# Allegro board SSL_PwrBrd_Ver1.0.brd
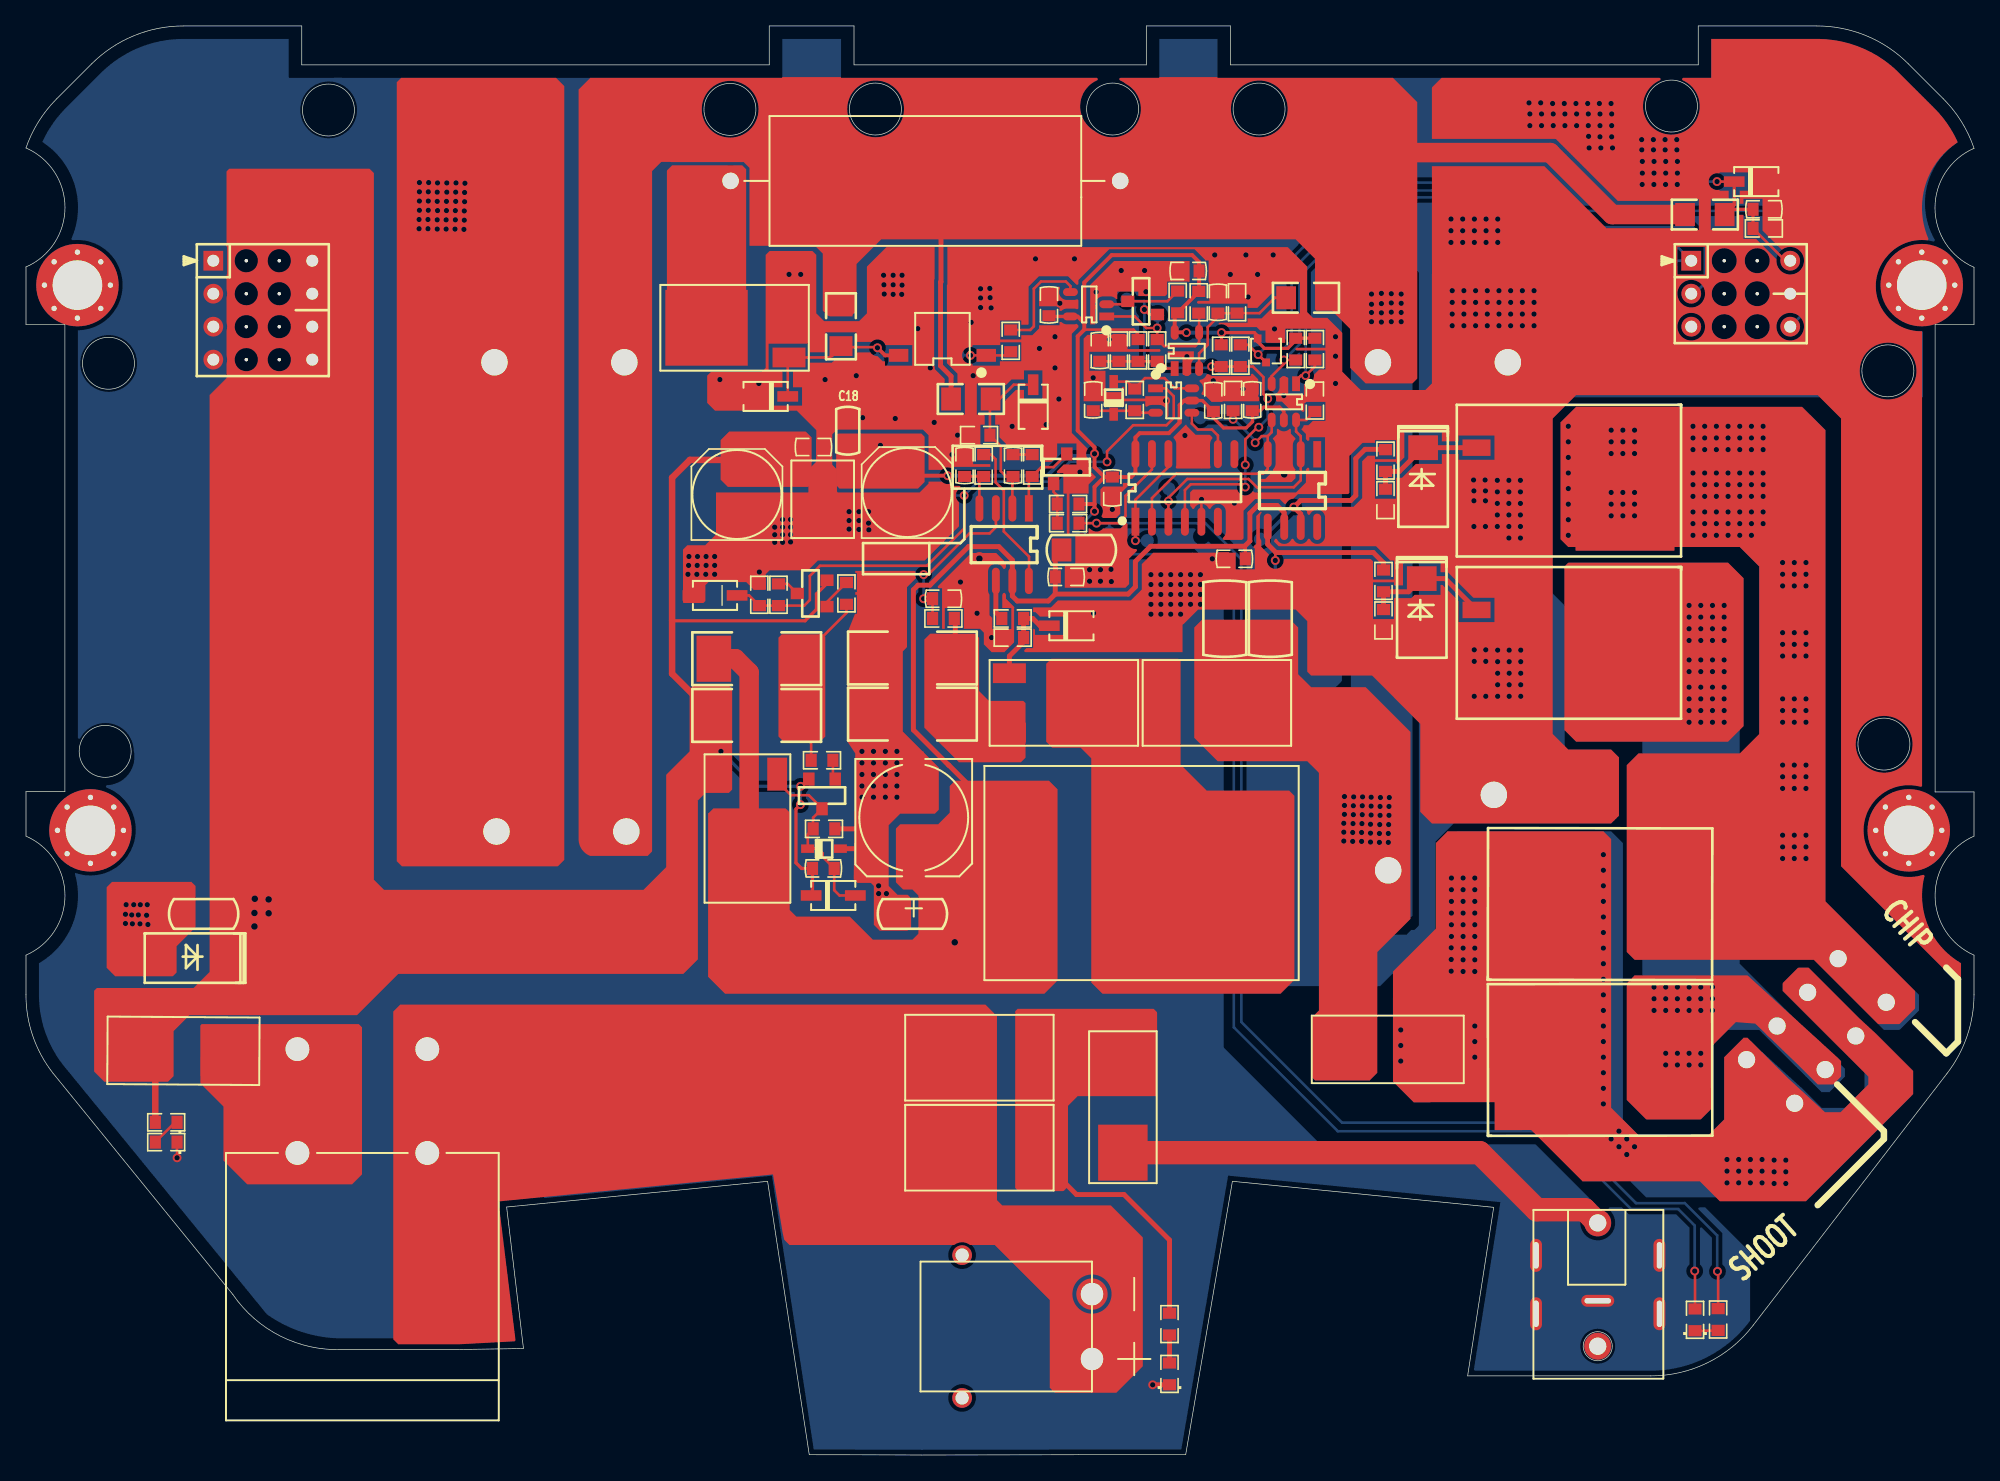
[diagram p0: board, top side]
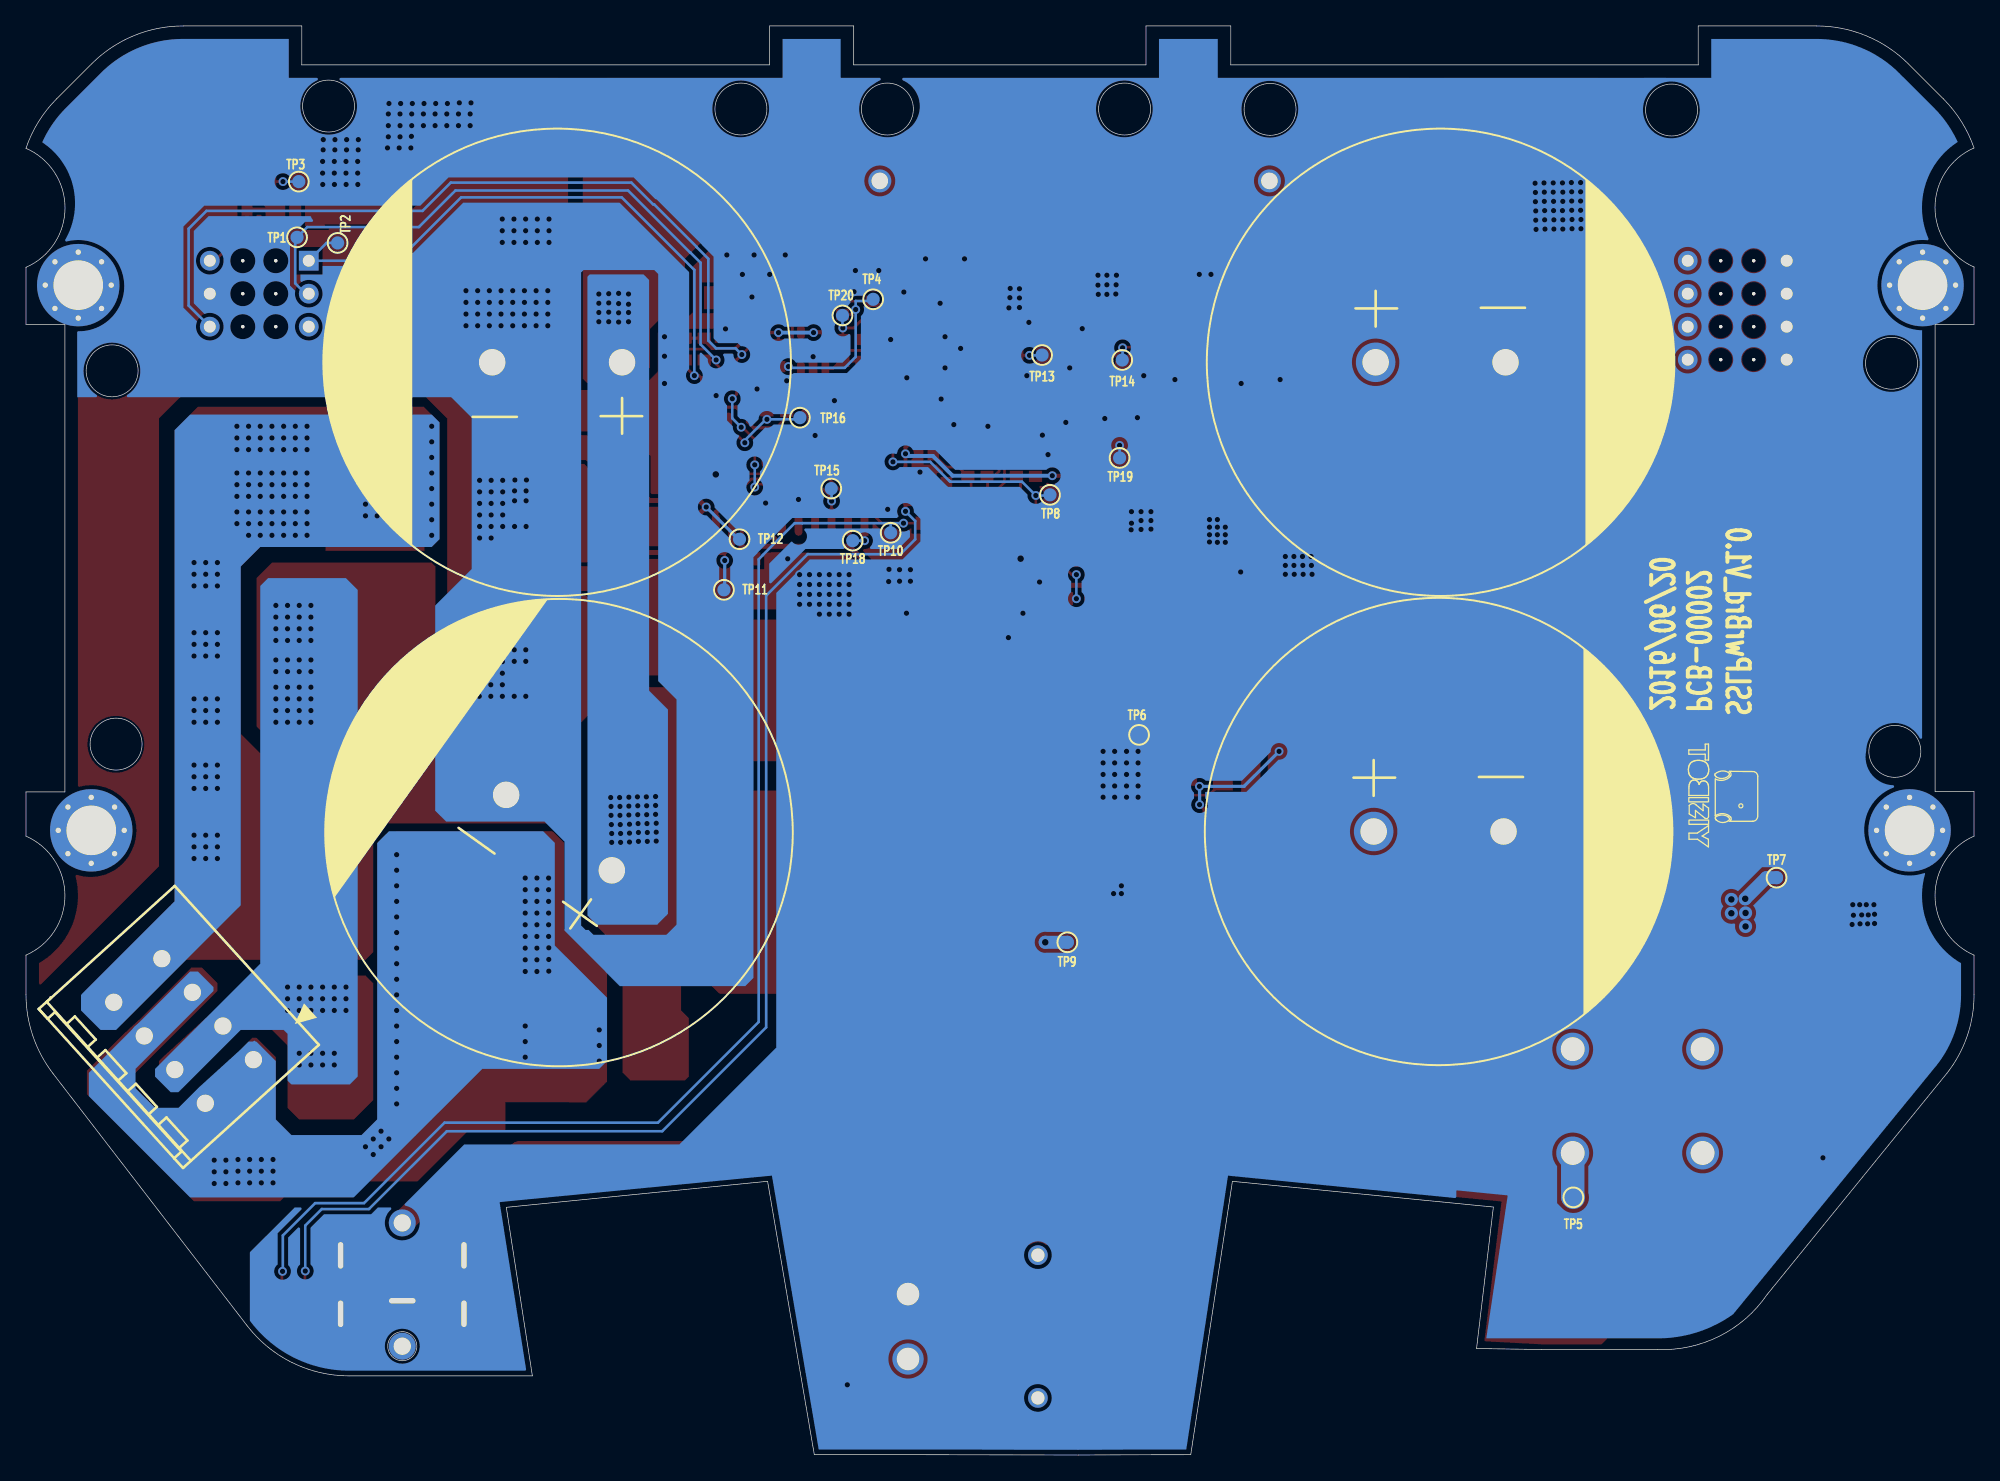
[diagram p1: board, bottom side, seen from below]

Outline 149.99 x 110.08 mm; copper layers: TOP, BOTTOM. Coordinates in mm from the lower left corner of the outline.
Outline path: circle c6.1,54.2 r2 ; circle c6.35,84.1 r2 ; circle c23.29,103.61 r2 ; circle c54.2,103.66 r2 ; circle c65.4,103.68 r2 ; circle c83.66,103.68 r2 ; circle c94.94,103.68 r2 ; circle c121.01,8.38 r1.12 ; circle c126.69,103.91 r2 ; circle c143.05,54.76 r2 ; circle c143.35,83.52 r2 ; 0,100.69 arc(3,96.1) 0,91.52 0,87.1 3,87.1 3,51.1 0,51.1 0,47.68 arc(3,43.09) 0,38.51 0,35.48 arc(0.53,32.27) 2.08,29.41 15.93,12.37 arc(19.61,9.15) 24.38,8.13 33.3,8.13 38.3,8.2 37.01,19.1 57.1,21.09 60.31,0.03 arc(64.64,0.02) 68.97,0 81.06,0.03 89.29,0.03 92.89,21.09 113,19.08 111,6.1 125.07,6.1 arc(129.49,7.12) 132.99,10.01 147.9,29.39 arc(149.45,32.26) 149.99,35.48 149.99,38.51 arc(146.99,43.09) 149.99,47.68 149.99,51.08 146.99,51.08 146.99,87.1 149.99,87.1 149.99,91.49 arc(146.98,96.08) 149.99,100.66 arc(149.03,102.7) 147.62,104.47 144.93,107.16 arc(141.68,109.34) 137.85,110.08 128.75,110.08 128.75,107.09 92.74,107.09 92.74,110.08 86.26,110.08 86.26,107.09 63.75,107.09 63.75,110.08 57.23,110.08 57.23,107.09 21.23,107.09 21.23,110.08 12.14,110.08 arc(8.31,109.33) 5.05,107.16 2.36,104.47 arc(0.97,102.71) 0,100.69 ; 2.5,90.12 arc(4,91.62) 5.5,90.12 arc(4,88.62) 2.5,90.12 ; 3.5,48.13 arc(5,49.63) 6.5,48.13 arc(5,46.63) 3.5,48.13 ; 143.5,48.13 arc(145,49.63) 146.5,48.13 arc(145,46.63) 143.5,48.13 ; 144.5,90.12 arc(146,91.62) 147.5,90.12 arc(146,88.62) 144.5,90.12

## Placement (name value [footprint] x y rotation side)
C1  10uF/35V  [1206_C]  13.68 41.68 180 top
C2  0.1uF  [0603_C]  61.39 45.19 0 top
C3  220uF/35V  [CAP_E_SMD_315]  68.35 49.1 90 top
C4  1500uF/200V  [EC-35]  109.09 84.18 0 bottom
C5  1500uF/200V  [EC-35]  41.07 84.18 180 bottom
C6  1500uF/200V  [EC-35]  108.95 47.95 35.6 bottom
C7  1500uF/200V  [EC-35]  41.22 48.03 180 bottom
C8  0.1uF  [0603_C]  80.09 67.64 180 top
C9  10uF/35V  [1206_C]  81.25 69.72 0 top
C10  2.2nF  [0603_C]  72.26 76.23 270 top
C11  10nF  [0603_C]  133.81 95.96 0 top
C12  10nF  [0603_C]  76 76.23 90 top
C13  470pF  [0603_C]  70.64 65.96 180 top
C14  2.2uF  [0603_C]  93.04 69.04 180 top
C15  0.1uF  [0603_C]  94.41 81.28 90 top
C16  47uF/35V  [CAP_E_SMD_250]  54.74 73.99 270 top
C17  1uF/50V  [0603_C]  60.63 77.65 180 top
C18  10uF  [0805_C]  63.27 78.92 270 top
C19  100uF/16V  [CAP_E_SMD_250]  67.84 74.14 270 top
C20  10nF  [0603_C]  82.68 85.09 270 top
C21  10nF  [0603_C]  91.77 88.8 90 top
C22  0.1uF  [0603_C]  89.48 91.21 180 top
C23  0.1uF  [0603_C]  78.77 88.6 90 top
C24  0.1uF  [0603_C]  91.41 81.23 90 top
C25  0.1uF  [0603_C]  83.64 74.5 270 top
C26  1uF  [0603_C]  82.17 81.28 90 top
C27  10uF/35V  [1206_C]  68.25 41.68 180 top
C28  0.22uF/250V  [1210_C]  92.3 64.19 90 top
C29  0.22uF/250V  [1210_C]  95.81 64.19 90 top
D1  4.3V  [SOD-123]  53.05 66.22 180 top
D2  MURD620CT  [TO252AA]  87.5 60.22 270 top
D3  MBRB20200CT  [TO263-2]  121.45 30.95 180.1 top
D4  12V  [SOD-123]  62.15 43.1 0 top
D5  LED  [0603_LED]  10.79 24.1 0 top
D6  SMBJ18A  [SMB]  12.83 38.28 0 top
D7  15V  [SOD-123]  80.49 63.88 0 top
D8  5.6V  [SOD-123]  77.55 80.75 270 top
D9  1N4148WS  [SOD-323]  61.44 46.71 180 top
D10  12V  [SOD-123]  56.95 81.55 180 top
D11  SMAJ16A  [SMB]  107.47 65.1 90 top
D12  MBRB20200CT  [TO263-2]  121.45 42.95 179.9 top
D13  3.3V  [SOD-123]  133.22 98.09 0 top
D14  SMAJ16A  [SMB]  107.57 75.18 90 top
D15  LED  [0603_LED]  128.51 10.41 270 top
D17  1N4148WS  [SOD-323]  83.74 81.43 270 top
D18  BAV99W  [SC70]  95.48 85.09 0 top
D19  LED  [0603_LED]  88.05 6.25 270 top
D20  MURD620CT  [TO252AA]  77.6 28.32 90 top
D21  MURD620CT  [TO252AA]  77.6 21.39 90 top
H1  HOLE  [HOLE_3]  3.96 90.12 0 top
H2  HOLE  [HOLE_3]  4.96 48.12 0 top
H3  HOLE  [HOLE_3]  145.96 90.12 0 top
H4  HOLE  [HOLE_3]  144.96 48.12 0 top
J1  HEADER2  [XT30PW-M]  82.08 9.9 90 top
J2  HEADER6  [POWER_DC2_5MM]  116.26 10.88 0 top
J4  HEADER 4X2  [SPT1_5-4P-H-3_5]  138.55 24.95 47.8 bottom
J5  HEADER 4X2  [HDR254MW-2X4]  16.96 92 270 top
J7  HEADER 3X2  [HDR254MW-2X3]  130.75 92 270 top
L1  68uH/6A  [L_DO5040H]  77.09 44.83 0 top
Q1  MMBT3906  [SOT23]  60.53 66.37 90 top
Q2  MMBT3906  [SOT23]  61.29 50.93 180 top
Q3  AOD4185  [TO252AA]  57.84 52.45 180 top
Q4  FQD18N20V2TM  [TO252AA]  75.72 60.22 270 top
Q5  FQD18N20V2TM  [TO252AA]  58.75 84.55 90 top
Q6  FDB082N15A  [TO263-2]  118.54 62.05 0 top
Q7  FDB082N15A  [TO263-2]  118.54 74.55 0 top
Q8  CES2302  [SOT23]  80.14 75.97 0 top
Q9  CES2302  [SOT23]  85.98 88.87 90 top
R1  33K  [0603_R]  57.94 66.27 270 top
R2  15K  [0603_R]  56.46 66.27 90 top
R3  10K  [0603_R]  63.17 66.37 270 top
R4  10K  [0603_R]  61.29 53.52 180 top
R5  10R  [2512_R]  52.96 56.97 0 top
R6  10R  [2512_R]  59.56 61.34 180 top
R7  5.1K  [0603_R]  10.79 25.63 0 top
R8  510K  [1206_R]  62.75 86.95 90 top
R9  150R  [RES_5W]  69.25 98.15 0 top
R10  270K  [1206_R]  72.75 81.35 180 top
R11  10R  [0603_R]  75.97 64.44 0 top
R12  10K  [0603_R]  75.97 62.97 0 top
R13  5.1K  [0603_R]  73.38 78.56 0 top
R14  10K  [0603_R]  61.44 48.23 0 top
R15  0.43R  [2512_R]  71.55 57.07 180 top
R16  0.43R  [2512_R]  71.55 61.39 180 top
R17  10R  [0603_R]  104.52 67.34 270 top
R18  249K  [1206_R]  129.26 95.55 180 top
R19  27K  [0603_R]  73.74 76.23 90 top
R20  10K  [0603_R]  104.52 64.29 90 top
R21  1K  [0603_R]  70.64 64.44 0 top
R22  5.1K  [0603_R]  133.81 94.49 180 top
R23  1K  [0603_R]  77.47 76.23 270 top
R24  100R  [0603_R]  80.24 71.78 0 top
R25  10R  [0603_R]  104.67 76.61 270 top
R26  10K  [0603_R]  80.24 73.25 180 top
R27  10K  [0603_R]  104.67 73.56 90 top
R28  5.1K  [0603_R]  92.94 81.28 270 top
R29  5.1K  [0603_R]  99.24 81.23 270 top
R30  510K  [0603_R]  87.1 85.09 270 top
R31  40.2K  [0603_R]  84.15 85.09 90 top
R32  10K  [0603_R]  85.62 85.09 90 top
R33  10K  [0603_R]  90.3 88.8 90 top
R34  200K  [1206_R]  98.55 89.15 0 top
R35  40.2K  [0603_R]  93.24 88.8 270 top
R36  2K  [0603_R]  75.82 85.83 90 top
R38  1K  [0603_R]  130.29 10.44 270 top
R39  5.1K  [0603_R]  99.24 85.19 90 top
R40  5.1K  [0603_R]  97.76 85.19 90 top
R41  100R  [0603_R]  93.5 84.68 90 top
R42  100K  [0603_R]  85.37 81.28 90 top
R43  3.3K  [0603_R]  92.02 84.68 270 top
R44  10K  [0603_R]  88.67 88.82 270 top
R45  5.1K  [0603_R]  88.05 10.08 270 top
SW1  -  [A8L-11-14N2]  25.9 23.27 180 top
TP1  TP  [TP6]  129.12 93.8 180 bottom
TP2  TP  [TP6]  125.99 93.37 180 bottom
TP3  TP  [TP6]  128.98 98.09 180 bottom
TP4  TP  [TP6]  84.76 89.03 180 bottom
TP5  TP  [TP6]  30.85 19.85 180 bottom
TP6  TP  [TP6]  64.29 55.47 180 bottom
TP7  TP  [TP6]  15.2 44.48 180 bottom
TP8  TP  [TP6]  71.15 73.97 180 bottom
TP9  TP  [TP6]  69.81 39.5 180 bottom
TP10  TP  [TP6]  83.41 71.04 180 bottom
TP11  TP  [TP6]  96.25 66.65 180 bottom
TP12  TP  [TP6]  95.05 70.55 180 bottom
TP13  TP  [TP6]  71.75 84.73 180 bottom
TP14  TP  [TP6]  65.58 84.35 180 bottom
TP15  TP  [TP6]  87.99 74.45 180 bottom
TP16  TP  [TP6]  90.4 79.91 180 bottom
TP18  TP  [TP6]  86.33 70.43 180 bottom
TP19  TP  [TP6]  65.79 76.81 180 bottom
TP20  TP  [TP6]  87.12 87.78 180 bottom
U1  15A  [1808_F_SOCKET]  15.62 31.12 179.6 top
U2  15A  [1808_F_SOCKET]  101.35 31.25 0 top
U3  EL357  [PC357]  70.56 85.98 180 top
U4  UC3843  [SO-8]  75.31 70.13 270 top
U5  SN74LVC2G04  [SOT23-6]  96.85 81.13 270 top
U6  MC34152D  [SO-8]  97.51 74.3 270 top
U7  78L05  [SOT89-3]  61.34 73.43 180 top
U8  LMV331  [SOT23-5]  89.38 85.09 90 top
U10  SN74LVC1G32  [SOT23-5]  81.81 88.65 180 top
U11  CD4072B  [SO-14]  89.23 74.5 90 top
U12  SN74LVC2G17  [SOT23-6]  88.37 81.23 0 top
U14  15A  [1808_F_SOCKET]  84.45 23.29 90 top

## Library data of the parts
C1 C2 C8-C15 C17 C18 C20-C29 = CAP NP
C3 = CAP P: User Part Number: CAPAE_315X405
C4-C7 C16 C19 = CAP P
D1 D4 = ZENER: User Part Number: SOD123
D2 D3 D12 D20 D21 = DIODE_DUAL_CC
D5 D15 D19 = LED
D6 D11 D14 = ZENER: room: M3
D7 D8 D10 D13 = ZENER: User Part Number: SOD123; room: M3
D9 D17 = DIODE: User Part Number: pn; Tolerance: RichardLC
D18 = DIODE_2X_S_SOT23: User Part Number: pn; Tolerance: RichardLC
H1-H4 = HOLE
J1 = HEADER2
J2 = HEADER6
J4 = HEADER 4X2
J5 = HEADER 4X2: User Part Number: pn; Tolerance: RichardLC
J7 = HEADER 3X2: User Part Number: pn; Tolerance: RichardLC
L1 = L
Q1 Q2 = PNP,SOT23
Q3 = PMOS,SOT23
Q4-Q9 = NMOS,SOT23
R1-R36 R38-R45 = RES_2
SW1 = SW_6
TP1-TP16 TP18-TP20 = TP
U1 U2 U14 = FUSE
U3 = PC357
U4 = UC3842
U5 = SN74LVC2G04
U6 = MC34152D
U7 = 78L15_SOT89
U8 = LMV331
U10 = SN74LVC1G32
U11 = CD4072B
U12 = SN74LVC2G17

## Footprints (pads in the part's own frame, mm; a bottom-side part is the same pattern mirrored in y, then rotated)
0603_C
  rect 0.864x1.016 smd: 1(-0.838,0) 2(0.838,0)
0603_LED
  rect 0.864x1.016 smd: 1(-0.838,0) 2(0.838,0)
0603_R
  rect 0.864x1.016 smd: 1(-0.838,0) 2(0.838,0)
0805_C
  rect 1.143x1.397 smd: 1(-0.991,0) 2(0.991,0)
1206_C
  rect 1.524x1.778 smd: 1(-1.524,0) 2(1.524,0)
1206_R
  rect 1.524x1.778 smd: 1(-1.524,0) 2(1.524,0)
1210_C
  rect 1.524x2.794 smd: 1(-1.524,0) 2(2.032,0)
1808_F_SOCKET
  rect 4.318x3.81 smd: 1(0,0) 2(7,0)
2512_R
  rect 2.667x3.556 smd: 1(0,0) 2(6.604,0)
A8L-11-14N2
  round 2.54 hole 1.829: 1(-5,0) 2(5,0) 3(-5,-8) 4(5,-8)
CAP_E_SMD_250
  rect 2.794x1.27 smd: 1(-2.667,0) 2(2.667,0)
CAP_E_SMD_315
  rect 3.937x1.524 smd: 1(-3.124,0) 2(3.124,0)
EC-35
  round 3.048 hole 2.032: 1(-5,0) 2(5,0)
HDR254MW-2X3
  round 0.254 hole 1.321 unplated: (0,2.54) (0,0) (2.54,2.54) (2.54,0) (5.08,2.54) (5.08,0)
  rect 1.524x1.524 hole 0.914: 1(0,-2.54)
  round 1.524 hole 0.914: 2(0,5.08) 3(2.54,-2.54) 4(2.54,5.08) 5(5.08,-2.54) 6(5.08,5.08)
HDR254MW-2X4
  round 0.254 hole 1.321 unplated: (0,2.54) (0,0) (2.54,2.54) (2.54,0) (5.08,2.54) (5.08,0) (7.62,2.54) (7.62,0)
  rect 1.524x1.524 hole 0.914: 1(0,-2.54)
  round 1.524 hole 0.914: 2(0,5.08) 3(2.54,-2.54) 4(2.54,5.08) 5(5.08,-2.54) 6(5.08,5.08) 7(7.62,-2.54) 8(7.62,5.08)
HOLE_3
  round 6.35 hole 3.81: 1(0,0)
  round 0.762 hole 0.406: 2(2.54,0) 3(1.796,1.796) 4(0,2.54) 5(-1.796,1.796) 6(-2.54,0) 7(-1.796,-1.796) 8(0,-2.54) 9(1.796,-1.796)
L_DO5040H
  rect 4.445x11.938 smd: 1(-0.65,0) 2(18.18,0)
PC357
  rect 1.499x0.991 smd: 1(-3.373,1.27) 2(-3.373,-1.27) 3(3.373,-1.27) 4(3.373,1.27)
POWER_DC2_5MM
  round 2.083 hole 1.321: (4.75,-2.5) 1(4.75,7)
  oval 2.54x0.914 hole 2.032x0.406: 2(4.75,1)
  oval 0.914x2.54 hole 0.406x2.032: 3(0,4.5) 4(9.5,4.5) 5(0,0) 6(9.5,0)
RES_5W
  round 1.778 hole 1.27: 1(-15,0) 2(15,0)
SC70
  rect 0.61x0.61 smd: 1(0.65,0.925) 2(-0.65,0.925) 3(0,-0.925)
SMB
  rect 1.905x2.286 smd: 1(-2.413,0) 2(2.413,0)
SO-8
  rect 2.032x0.61 smd: 1(-2.794,1.905)
  oval 2.032x0.61 smd: 2(-2.794,0.635) 3(-2.794,-0.635) 4(-2.794,-1.905) 5(2.794,-1.905) 6(2.794,-0.635) 7(2.794,0.635) 8(2.794,1.905)
SO-14
  rect 2.159x0.61 smd: 1(-2.603,3.81)
  oval 2.159x0.61 smd: 2(-2.603,2.54) 3(-2.603,1.27) 4(-2.603,0) 5(-2.603,-1.27) 6(-2.603,-2.54) 7(-2.603,-3.81) 8(2.603,-3.81) 9(2.603,-2.54) 10(2.603,-1.27) 11(2.603,0) 12(2.603,1.27) 13(2.603,2.54) 14(2.603,3.81)
SOD-123
  rect 1.6x0.813 smd: 1(1.702,0) 2(-1.702,0)
SOD-323
  rect 1.016x0.66 smd: 1(-1.252,0) 2(1.252,0)
SOT23
  rect 0.889x1.016 smd: 1(-1.016,-1.143) 2(1.016,-1.143) 3(0,1.143)
SOT23-5
  rect 1.143x0.61 smd: 1(-1.397,0.94)
  oval 1.143x0.61 smd: 2(-1.397,0) 3(-1.397,-0.94) 4(1.397,-0.94) 5(1.397,0.94)
SOT23-6
  rect 1.143x0.61 smd: 1(-1.397,0.94)
  oval 1.143x0.61 smd: 2(-1.397,0) 3(-1.397,-0.94) 4(1.397,-0.94) 5(1.397,0) 6(1.397,0.94)
SOT89-3
  rect 0.991x1.499 smd: 1(-1.549,-2.134) 3(1.549,-2.134)
  custom 0.55x0.55 smd: 2(0,-2.134)
SPT1_5-4P-H-3_5
  rect 2.083x2.083 hole 1.321: 1(0,-8.2)
  round 2.083 hole 1.321: 2(0,-3.2) 3(3.5,-8.2) 4(3.5,-3.2) 5(7,-8.2) 6(7,-3.2) 7(10.5,-8.2) 8(10.5,-3.2)
TO252AA
  rect 1.524x2.54 smd: 1(0,0) 2(4.572,0)
  rect 5.842x6.35 smd: 3(2.286,6.35)
TO263-2
  rect 2.159x1.27 smd: 1(-6.858,3.048) 2(-6.858,-2.032)
  rect 7.62x10.795 smd: 3(4.572,0.508)
TP6
  round 1.016 smd: 1(0,0)
XT30PW-M
  round 1.524 hole 1.016: (-5.5,10) (5.5,10)
  round 2.413 hole 1.727: 1(-2.5,0) 2(2.5,0)

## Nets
+5V: C15.1 C18.2 C19.1 C22.1 C23.1 C24.1 C25.1 D15.1(ANODE) D18.2 R26.1 R32.2 R33.2 R39.2 R40.2 R43.1 R44.2 TP19.1 U5.5(VCC) U7.1(OUT) U8.5(V+) U10.5(VCC) U11.14(VDD) U12.5(VCC)
+16V: C1.1 C2.1 C16.1 C17.2 D4.2(CATHODE) D6.2(CATHODE) J5.2 J5.4 J5.6 J5.8 Q1.2(E) Q2.2(E) Q3.2(SOURCE) R5.1 R7.1 TP7.1 U1.2 U7.3(VIN)
+16V_2: C3.1 C8.2 C9.1 C14.1 C27.1 L1.1 Q3.3(DRAIN) R6.2 TP9.1 U4.7(VI) U6.6(VCC)
GND: C1.2 C3.2 C4.2 C5.2 C6.2 C7.2 C8.1 C9.2 C10.1 C11.2 C13.1 C14.2 C15.2 C16.2 C17.1 C18.1 C19.2 C20.1 C21.2 C22.2 C23.2 C24.2 C25.2 C26.2 C27.2 C28.2 C29.2 D1.1(ANODE) D5.2(CATHODE) D6.1(ANODE) D7.1(ANODE) D8.1(ANODE) D9.1(A) D10.1(ANODE) D11.1(ANODE) D13.1(ANODE) D14.1(ANODE) D18.1 D19.2(CATHODE) J1.2 J2.2 J2.3 J2.4 J2.5 J2.6 J5.1 J5.3 J5.5 J5.7 J7.4 Q5.2(SOURCE) Q6.2(SOURCE) Q7.2(SOURCE) Q8.2(SOURCE) Q9.2(SOURCE) R2.2 R12.1 R13.1 R14.2 R15.2 R16.2 R20.1 R22.1 R27.1 R28.1 R29.1 R31.2 R35.1 TP6.1 U3.2 U3.3 U4.5(GND) U5.2(GND) U6.3(GND) U7.2(GND) U8.2(V-) U10.3(GND) U11.5(1D) U11.7(GND) U11.10(2B) U11.11(2C) U12.2(GND)
+BAT: D20.3 D21.3 J1.1 SW1.1 SW1.3 TP5.1
+VCAP: C4.1 C5.1 C6.1 C7.1 C28.1 C29.1 D2.3 R8.2 R9.2 R10.2 R18.2 R34.2 U2.1
+VCOIL: D3.3 D12.3 J4.1 J4.2 J4.5 J4.6 U2.2
BOOST_EN: R24.2 R38.1 TP10.1 U11.13(2Y)
BOOST_EN_1: TP18.1 U11.1(1Y) U11.12(2D)
CAP_LOW: R30.1 R33.1 TP20.1 U8.4(OUT) U10.1(A)
CAP_V_OUT: C11.1 D13.2(CATHODE) J7.2 R18.1 R22.2 TP3.1
CHG_END: D1.2(CATHODE) R1.2 R2.1 TP8.1 U12.1(1A)
CHIP: R29.2 TP15.1 U5.6(1Y) U6.2(IN_A) U11.3(1B)
CHIP_DRV: R25.1 TP12.1 U6.7(OUT_A)
CHIP_IN: J7.1 R39.1 TP2.1 U5.1(1A)
COIL_CHIP: D12.1 D12.2 J4.7 J4.8 Q7.3(DRAIN)
COIL_SHOOT: D3.1 D3.2 J4.3 J4.4 Q6.3(DRAIN)
DIS_SW: Q9.1(GATE) R41.1 R43.2 TP4.1 U11.4(1C)
DISCHARGE: R36.1 TP13.1 U3.1
PWR_OK: U11.9(2A) U12.4(2Y)
SHOOT: R28.2 TP16.1 U5.4(2Y) U6.4(IN_B) U11.2(1A)
SHOOT_DRV: R17.1 TP11.1 U6.5(OUT_B)
SHOOT_IN: J7.3 R40.1 TP1.1 U5.3(2A)
VFB: C12.1 D8.2(CATHODE) R10.1 R13.2 U4.2(VFB)
N00647: C2.2 D4.1(ANODE) D9.2(K) Q2.3(C) Q3.1(GATE) R14.1
N02314: R3.2 R4.2 R5.2 R6.1
N04713: Q2.1(B) R4.1
N04752: Q1.1(B) R3.1
N05183: Q1.3(C) R1.1
N5273417: D5.1(ANODE) R7.2
N5276714: R19.2 U4.8(VREF)
N5277105: C10.2 R19.1 U4.4(RT/CT)
N5278068: Q8.3(DRAIN) R23.2 U4.1(COMP)
N5278284: C12.2 R23.1
N5280051: Q8.1(GATE) R24.1 R26.2
N11462968: D2.1 D2.2 L1.2 Q4.3(DRAIN)
N11463163: Q4.2(SOURCE) R15.1 R16.1 R21.2
N11464709: D7.2(CATHODE) Q4.1(GATE) R11.2 R12.2
N11468710: R11.1 U4.6(OUTPUT)
N11471960: C13.2 R21.1 U4.3(ISEN)
N11488509: D11.2(CATHODE) Q6.1(GATE) R17.2 R20.2
N11493133: D14.2(CATHODE) Q7.1(GATE) R25.2 R27.2
N11962195: Q5.3(DRAIN) R9.1
N11967817: D10.2(CATHODE) Q5.1(GATE) R8.1 TP14.1 U3.4
N12014213: C26.1 D17.2(K) R42.1 U12.3(2A)
N12020233: D17.1(A) R42.2 U12.6(1Y)
N12029339: D15.2(CATHODE) R38.2
N12095362: C21.1 R34.1 R35.2 U8.3(-IN)
N12099460: C20.2 R30.2 R31.1 R32.1 U8.1(+IN)
N12127491: Q9.3(DRAIN) R44.1 U10.2(B)
N12133632: R36.2 U10.4(Y)
N12190959: SW1.2 SW1.4 U1.1
N12237973: D18.3 J7.6 R41.2
N12300785: H1.1 H1.2 H1.3 H1.4 H1.5 H1.6 H1.7 H1.8 H1.9
N12300857: H2.1 H2.2 H2.3 H2.4 H2.5 H2.6 H2.7 H2.8 H2.9
N12300959: H3.1 H3.2 H3.3 H3.4 H3.5 H3.6 H3.7 H3.8 H3.9
N12301091: H4.1 H4.2 H4.3 H4.4 H4.5 H4.6 H4.7 H4.8 H4.9
N12384738: D19.1(ANODE) R45.2
N12384949: D20.1 D20.2 D21.1 D21.2 R45.1 U14.2
N12400429: J2.1 U14.1

Pads without a net: J7 5; U6 1 8; U11 6 8

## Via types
v1: diameter 0.686, hole 0.406, TOP to BOTTOM, 713 vias
v2: diameter 1.016, hole 0.508, TOP to BOTTOM, 8 vias

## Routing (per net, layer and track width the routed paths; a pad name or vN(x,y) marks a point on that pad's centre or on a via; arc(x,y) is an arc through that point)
+5V: length 190.9
  TOP w0.203: D15.1 128.51,14.15 v1(128.48,14.17) ; R32.2 85.62,86.33 85.27,86.69 81.48,86.69
  TOP w0.254: U12.5 90.58,81.23 C24.1 91.41,79.91 92.2,79.12 93.95,79.12 94.44,79.6 94.44,80.42 C15.1 95.02,80.44 95.3,80.72 96.52,80.72 96.85,80.39 U5.5 ; R43.1 92.05,85.55 v1(92.05,86.46) 94.57,86.46 94.83,86.21 D18.2 94.83,85.77 95.35,85.25 97.15,85.25 97.76,85.86 R40.2 R39.2 ; 80.98,87.71 78.82,87.71 C23.1
  TOP w0.305: 81.48,87.2 81.48,86.69 80.98,86.18 80.98,78.92 82.27,77.63 v1(82.27,77.13) 82.27,76.1 83.03,75.34 ; 81.48,87.2 80.98,87.71 ; 81.48,87.2 81.48,90.32 83.59,92.43 89.79,92.43 90.32,91.9 C22.1 90.32,89.66 R33.2 90.3,89.61 R44.2 88.44,87.76 U8.5 89.32,86.49 v1(89.35,86.46) ; U12.5 89.18,81.23 88.82,80.87 88.82,79.69 88.82,79.54 88,78.71 85.75,78.71 85.42,78.38 U11.14 85.42,75.67 85.09,75.34 C25.1 83.03,75.34 ; 83.03,75.34 82.27,74.57 82.27,73.25 ; 68.94,75.44 v1(70.97,75.44) ; 82.27,73.25 R26.1 ; 82.27,73.25 v1(82.27,72.69)
  BOTTOM w0.203: v1(82.27,72.69) 81.52,71.95 81.52,70.54 82.67,69.39 89.8,69.39 93,66.2 93,32.94 101,24.94 117.59,24.94 123.58,18.95 127.21,18.95 128.48,17.68 v1(128.48,14.17) ; TP19.1 v1(65.79,77.78)
  BOTTOM w0.305: v1(82.27,77.13) 82.11,76.96 80.16,76.96 78.64,75.44 v1(70.97,75.44) ; v1(92.05,86.46) v1(89.35,86.46)
+16V: length 67.7
  TOP w0.25: 49.75,64.31 49.8,64.26 59.98,64.26 60.86,65.14 60.86,66.33 61.67,67.14 Q1.2
  TOP w0.254: v1(59.64,51.51) 59.72,51.51 Q2.2 ; D4.2 60.55,43.21 C2.1 59.72,45.19 59.28,45.62 59.28,49.76 v1(59.63,50.1)
  TOP w0.5: U1.2 9.96,29.82 R7.1 ; R5.1 49.75,60.18 49.75,75.29 51.12,76.66 C16.1
  TOP w1: 17.52,41.68 v2(17.59,41.76)
  BOTTOM w0.203: v1(59.64,51.51) 59.64,50.11 v1(59.63,50.1)
  BOTTOM w0.25: v1(59.64,51.51) 56.2,51.51 v1(53.51,54.2)
  BOTTOM w0.254: v1(59.64,51.51) 59.63,51.5 v1(59.63,50.1)
  BOTTOM w1: TP7.1 15.99,44.48 v2(17.62,42.85)
  vias: v2(17.59,40.72) v2(18.68,42.8) v2(18.68,41.73)
+16V_2: length 80.9
  TOP w0.254: 93.83,70 93.88,69.95 C14.1
  TOP w0.381: 79.25,66.32 C8.2 79.25,69.24 C9.1 ; 79.25,66.32 84.86,66.32 85.42,66.88 85.42,68.83 86.59,70 93.83,70 94.23,70.41 94.23,72.54 94.84,73.15 96.32,73.15 96.88,72.59 U6.6 ; 79.25,66.32 78.71,65.79 76.33,65.79 75.95,66.17 U4.7 75.95,68.94 74.9,69.98 72.57,69.98 69.6,67.01 68.68,67.01 68.33,66.65 68.33,55.85 71.04,53.14 71.06,53.14 72.85,51.35
  TOP w1.5: Q3.3 55.68,46.23 55.68,60.28 54.62,61.34 R6.2
  BOTTOM w1: TP9.1 v2(71.51,39.5)
GND: length 45.1
  TOP w0.203: v1(90.51,73.61) 90.5,73.6 U11.5 ; v1(94.09,89.2) 93.75,89.2 93.32,89.64 R35.1 C21.2 ; Q8.2 v1(81.15,75.72) ; C23.2 78.89,89.43 v1(79.6,88.72) ; D5.2 v1(11.63,22.9) ; C13.1 71.48,66.77 v1(71.95,67.25) ; R2.2 v1(56.46,68.02) ; D18.1 v1(96.13,86.75) ; C25.2 v1(83.64,72.85)
  TOP w0.254: R13.1 v1(71.73,78.56) ; U10.3 v1(82.4,89.59) ; U11.7 v1(93.04,73.33) ; C14.2 v1(91.34,69.04) ; C10.1 v1(71.3,77.06) ; U11.10 U11.11 v1(89.23,78.54) ; C22.2 87.93,91.21 87.12,90.4 Q9.2 86.84,89.61 v1(86.23,89.61)
  TOP w0.305: C26.2 v1(82.17,82.98) ; R31.2 v1(83.41,85.93) C20.1 ; U8.2 v1(89.38,84.61) ; R28.1 v1(93.7,82.12) C15.2 ; C24.2 v1(91.41,82.75) ; U3.2 v1(72.77,87.25) ; v1(87.74,81.22) 87.74,81.23 U12.2
  TOP w0.381: D19.2 v1(86.75,5.41) ; C18.1 v1(64.41,79.91) ; D7.1 v1(82.19,64.85) ; U5.2 v1(96.85,81.61) 97.23,81.23 98.4,81.23 R29.1 ; R14.2 64.08,48.23 64.11,48.26 ; 64.14,46.69 64.11,46.71 D9.1 ; U6.3 v2(96.88,75.54) ; U4.5 v2(73.41,69.05) ; R12.1 v1(74.35,62.97)
  BOTTOM w0.203: 127.53,88.25 127.6,88.32
  BOTTOM w0.25: 89.55,34.59 89.55,35.38
  vias: v1(7.71,42.39) v1(7.66,41.66) v1(7.66,40.95) v1(8.14,41.61) v1(8.19,40.92) v1(8.29,42.39) v1(8.65,41.61) v1(8.8,42.39) v1(8.78,40.92) v1(9.29,41.58) v1(9.34,42.39) v1(9.39,40.87) v1(30.29,98.02) v1(30.29,97.31) v1(30.29,96.6) v1(30.29,95.89) v1(30.27,95.17) v1(30.27,94.46) v1(31,98.02) v1(30.98,97.31) v1(30.98,96.6) v1(30.98,95.89) v1(30.95,95.17) v1(30.95,94.46) v1(31.69,97.99) v1(31.66,97.28) v1(31.66,96.57) v1(31.69,95.86) v1(31.66,95.15) v1(31.66,94.44) v1(32.4,97.99) v1(32.4,97.28) v1(32.37,96.57) v1(32.37,95.86) v1(32.35,95.15) v1(32.35,94.44) v1(33.11,97.99) v1(33.09,97.28) v1(33.09,96.57) v1(33.06,95.86) v1(33.06,95.15) v1(33.03,94.44) v1(33.8,97.97) v1(33.77,97.26) v1(33.77,96.55) v1(33.75,95.83) v1(33.75,95.12) v1(33.72,94.41) v1(50.97,67.84) v1(51.04,69.22) v1(51.02,68.53) v1(51.7,69.22) v1(51.68,68.53) v1(51.65,67.84) v1(52.36,69.22) v1(52.36,68.53) v1(52.34,67.84) v1(53.02,69.22) v1(53.02,68.53) v1(53.02,67.84) v1(53.43,82.84) v1(56.43,82.54) v1(57.65,71.48) v1(57.65,70.89) v1(57.65,70.31) v1(58.26,72.06) v1(58.26,71.48) v1(58.26,70.89) v1(58.26,70.31) v1(58.75,90.95) v1(58.87,72.06) v1(58.87,71.48) v1(58.87,70.89) v1(58.87,70.33) v1(59.65,90.95) v1(61.53,82.84) v1(63.37,72.67) v1(63.37,71.98) v1(63.37,71.32) v1(63.93,83.14) v1(64.14,72.67) v1(64.14,71.98) v1(64.14,71.3) v1(64.36,54.2) v1(64.36,53.31) v1(64.36,52.43) v1(64.36,51.54) v1(64.36,50.67) v1(64.87,72.67) v1(64.87,71.78) v1(64.9,71.27) v1(65.25,54.2) v1(65.25,53.31) v1(65.25,52.43) v1(65.25,51.54) v1(65.25,50.67) v1(65.65,43.85) v1(65.65,43.25) v1(66.03,90.88) v1(66.05,90.14) v1(66.08,89.43) v1(66.17,54.2) v1(66.17,53.31) v1(66.17,52.43) v1(66.17,51.54) v1(66.17,50.67) v1(66.25,43.25) v1(66.77,90.88) v1(66.77,90.14) v1(66.77,89.41) v1(66.93,79.84) v1(67.06,54.2) v1(67.06,53.31) v1(67.06,52.43) v1(67.06,51.54) v1(67.06,50.67) v1(67.45,90.88) v1(67.45,90.12) v1(67.43,89.41) v1(68.66,86.77) v1(69.63,83.74) v1(69.93,79.54) v1(72.93,83.14) v1(73.23,64.84) v1(73.5,89.84) v1(73.5,89.13) v1(73.5,88.39) v1(74.21,89.87) v1(74.23,89.15) v1(74.31,88.37) v1(75.93,79.24) v1(77.73,92.14) v1(78.03,85.24) v1(78.55,79.38) v1(79.23,86.14) v1(79.23,83.74) v1(79.53,81.34) v1(80.73,92.14) v1(81.89,68.2) v1(81.89,67.31) v1(82.73,68.2) v1(82.73,67.31) v1(83.54,68.22) v1(83.57,67.28) v1(84.33,91.24) v1(86.13,91.24) v1(86.61,67.82) v1(86.61,67.06) v1(86.61,66.29) v1(86.61,65.53) v1(86.61,64.77) v1(87.38,67.82) v1(87.38,67.06) v1(87.38,66.29) v1(87.38,65.53) v1(87.38,64.77) v1(88.14,67.82) v1(88.14,67.06) v1(88.14,66.29) v1(88.14,65.53) v1(88.14,64.77) v1(88.9,67.82) v1(88.9,67.06) v1(88.9,66.29) v1(88.9,65.53) v1(88.9,64.77) v1(89.66,67.82) v1(89.66,67.06) v1(89.66,66.29) v1(89.66,65.53) v1(90.42,67.82) v1(90.42,67.06) v1(90.42,66.29) v1(90.42,65.53) v1(91.53,92.44) v1(92.73,90.94) v1(93.93,92.44) v1(94.83,90.94) v1(96.03,92.44) v1(100.83,86.14) v1(100.83,84.64) v1(100.83,82.54) v1(109.72,95.21) v1(109.72,94.31) v1(109.72,93.41) v1(109.81,89.69) v1(109.81,88.79) v1(109.81,87.89) v1(109.81,86.99) v1(110.62,95.21) v1(110.62,94.31) v1(110.62,93.41) v1(110.71,89.69) v1(110.71,88.79) v1(110.71,87.89) v1(110.71,86.99) v1(111.46,75.11) v1(111.48,74.27) v1(111.48,73.51) v1(111.48,71.53) v1(111.51,62.03) v1(111.51,61.14) v1(111.51,58.45) v1(111.52,95.21) v1(111.52,94.31) v1(111.52,93.41) v1(111.61,89.69) v1(111.61,88.79) v1(111.61,87.89) v1(111.61,86.99) v1(112.34,75.11) v1(112.37,74.27) v1(112.37,73.51) v1(112.37,71.53) v1(112.39,62.03) v1(112.39,61.14) v1(112.39,58.45) v1(112.42,95.21) v1(112.42,94.31) v1(112.42,93.41) v1(112.51,89.69) v1(112.51,88.79) v1(112.51,87.89) v1(112.51,86.99) v1(113.28,75.08) v1(113.28,74.19) v1(113.28,73.3) v1(113.28,72.42) v1(113.28,71.53) v1(113.31,62) v1(113.31,61.11) v1(113.31,60.22) v1(113.31,59.33) v1(113.31,58.45) v1(113.32,95.21) v1(113.32,94.31) v1(113.32,93.41) v1(113.41,89.69) v1(113.41,88.79) v1(113.41,87.89) v1(113.41,86.99) v1(114.17,75.08) v1(114.17,74.19) v1(114.17,73.3) v1(114.17,72.42) v1(114.17,71.53) v1(114.17,70.64) v1(114.2,62) v1(114.2,61.11) v1(114.2,60.22) v1(114.2,59.33) v1(114.2,58.45) v1(114.31,89.69) v1(114.31,88.79) v1(114.31,87.89) v1(114.31,86.99) v1(115.06,75.08) v1(115.06,74.19) v1(115.06,73.3) v1(115.06,72.42) v1(115.06,71.53) v1(115.06,70.64) v1(115.09,62) v1(115.09,61.11) v1(115.09,60.22) v1(115.09,59.33) v1(115.09,58.45) v1(115.21,89.69) v1(115.21,88.79) v1(115.21,87.89) v1(115.21,86.99) v1(115.72,104.16) v1(115.79,103.3) v1(115.79,102.4) v1(116.11,89.69) v1(116.11,88.79) v1(116.11,87.89) v1(116.11,86.99) v1(116.62,104.16) v1(116.69,103.3) v1(116.69,102.4) v1(117.54,104.11) v1(117.59,103.3) v1(117.59,102.4) v1(118.44,104.11) v1(118.49,103.3) v1(118.49,102.4) v1(119.34,104.11) v1(119.39,103.3) v1(119.39,102.4) v1(120.24,104.11) v1(120.29,103.3) v1(120.29,102.4) v1(120.31,101.58) v1(120.35,100.69) v1(121.14,104.11) v1(121.19,103.3) v1(121.19,102.4) v1(121.19,101.54) v1(121.25,100.69) v1(122.04,104.11) v1(122.09,103.3) v1(122.09,102.4) v1(122.09,101.54) v1(122.15,100.69) v1(124.4,101.33) v1(124.41,100.54) v1(124.45,99.65) v1(124.45,98.75) v1(124.44,97.87) v1(125.3,101.33) v1(125.31,100.54) v1(125.35,99.65) v1(125.35,98.75) v1(125.34,97.87) v1(126.2,101.33) v1(126.21,100.54) v1(126.25,99.65) v1(126.25,98.75) v1(126.24,97.87) v1(127.1,101.33) v1(127.11,100.54) v1(127.15,99.65) v1(127.15,98.75) v1(127.14,97.87)
+BAT: length 3.4
  BOTTOM w1.8: SW1.1 30.9,19.9 TP5.1
+VCAP: length 38.5
  TOP w0.203: C5.1 46.22,84.02
  TOP w0.381: 70.37,94.79 70.45,94.72 70.45,90.37 70.42,90.34 70.42,83.9 71.23,83.09 R10.2
  TOP w1.5: R18.2 122.12,95.55 117.35,100.33 105.28,100.33
  vias: v1(101.46,48.67) v1(101.46,47.98) v1(101.46,47.3) v1(101.51,50.72) v1(101.51,50.04) v1(101.51,49.35) v1(102.2,50.01) v1(102.2,49.33) v1(102.17,48.64) v1(102.15,47.96) v1(102.15,47.27) v1(102.22,50.7) v1(102.91,50.7) v1(102.88,50.01) v1(102.88,49.33) v1(102.86,48.64) v1(102.83,47.96) v1(102.83,47.27) v1(103.6,89.43) v1(103.6,88.65) v1(103.6,88.01) v1(103.6,87.3) v1(103.57,50.67) v1(103.57,49.99) v1(103.57,49.3) v1(103.52,48.59) v1(103.52,47.9) v1(103.52,47.22) v1(104.21,47.88) v1(104.21,47.19) v1(104.28,50.65) v1(104.26,49.96) v1(104.26,49.28) v1(104.23,48.56) v1(104.36,89.48) v1(104.36,88.7) v1(104.36,87.99) v1(104.36,87.27) v1(104.89,47.88) v1(104.89,47.19) v1(104.97,50.65) v1(104.94,49.96) v1(104.94,49.28) v1(104.92,48.56) v1(105.12,89.46) v1(105.12,88.75) v1(105.12,88.04) v1(105.12,87.3) v1(105.88,89.43) v1(105.88,88.72) v1(105.88,88.01) v1(105.88,87.3)
+VCOIL:
  vias: v1(105.85,32.75) v1(105.85,31.55) v1(105.85,30.35) v1(109.75,44.45) v1(109.75,43.55) v1(109.75,42.65) v1(109.75,41.75) v1(109.75,40.85) v1(109.75,39.95) v1(109.73,39.07) v1(109.73,38.17) v1(109.73,37.27) v1(110.65,44.45) v1(110.65,43.55) v1(110.65,42.65) v1(110.65,41.75) v1(110.65,40.85) v1(110.65,39.95) v1(110.65,39.05) v1(110.65,38.15) v1(110.65,37.25) v1(111.55,44.45) v1(111.55,43.55) v1(111.55,42.65) v1(111.55,41.75) v1(111.55,40.85) v1(111.55,39.95) v1(111.55,39.05) v1(111.55,38.15) v1(111.55,37.25) v1(111.55,33.05) v1(111.55,31.85) v1(111.55,30.65) v1(121.45,46.25) v1(121.45,45.05) v1(121.45,43.85) v1(121.45,42.65) v1(121.45,41.45) v1(121.45,40.25) v1(121.45,39.05) v1(121.45,37.85) v1(121.45,36.65) v1(121.45,35.45) v1(121.45,34.25) v1(121.45,33.05) v1(121.45,31.85) v1(121.45,30.65) v1(121.45,29.45) v1(121.45,28.25) v1(121.45,27.05) v1(122.05,24.35) v1(122.65,24.95) v1(122.65,23.75) v1(123.25,24.35) v1(123.25,23.15) v1(123.85,23.75) v1(130.97,22.77) v1(130.97,21.87) v1(130.97,20.97) v1(131.87,22.77) v1(131.87,21.87) v1(131.87,20.97) v1(132.77,22.77) v1(132.77,21.87) v1(132.77,20.97) v1(133.67,22.77) v1(133.67,21.87) v1(133.67,20.97) v1(134.59,22.72) v1(134.59,21.82) v1(134.59,20.92) v1(135.49,22.72) v1(135.49,21.82) v1(135.49,20.92)
BOOST_EN: length 107.2
  TOP w0.203: R24.2 v1(82.42,71.78) 84.1,71.78 84.66,72.34 84.66,73.89 86.11,75.34 86.69,75.92 U11.13 ; v1(130.23,14.15) 130.29,14.1 R38.1
  BOTTOM w0.203: TP10.1 83.41,71.78 ; 83.41,71.78 90.21,71.78 90.8,71.78 93.25,69.34 93.25,69.32 93.57,69 93.57,33.36 101.33,25.6 117.76,25.6 123.96,19.41 127.72,19.41 130.21,16.92 130.21,14.17 v1(130.23,14.15) ; 83.41,71.78 v1(82.42,71.78)
BOOST_EN_1: length 8.6
  TOP w0.203: U11.12 87.96,76.12 85.42,73.58 U11.1 v1(85.42,70.43)
  BOTTOM w0.203: v1(85.42,70.43) TP18.1
CAP_LOW: length 11.9
  TOP w0.203: 83.21,87.71 85.37,87.71 86.26,86.82 v1(87.1,86.82) R30.1 87.12,85.93 87.63,85.42 90.02,85.42 90.32,85.73 U8.4 90.32,87.94 R33.1
  BOTTOM w0.203: TP20.1 87.12,86.84 v1(87.1,86.82)
CAP_V_OUT: length 12.5
  TOP w0.203: R22.2 135.46,92 J7.2 ; v1(130.2,98.09) D13.2
  TOP w0.25: D13.2 131.52,96.29 131.19,95.96 ; R22.2 C11.1 131.19,95.96 ; 131.19,95.96 R18.1
  BOTTOM w0.203: TP3.1 v1(130.2,98.09)
CHG_END: length 47.4
  TOP w0.203: D1.2 55.68,66.22 R2.1 R1.2 59.92,65.43 60.35,65.86 60.35,67.72 61.14,68.5 69.37,68.5 72.24,71.37 v1(72.24,73.91) ; v1(83.24,76.5) 83.24,77.32 85.24,79.32 87.81,79.32 88.37,79.88 88.37,81.56 87.76,82.17 U12.1
  BOTTOM w0.203: TP8.1 71.2,73.91 v1(72.24,73.91) 73.3,74.98 78.83,74.98 78.9,75.05 78.91,75.05 80.37,76.5 v1(83.24,76.5)
CHIP: length 20.6
  TOP w0.203: U11.3 v1(87.96,73.48) 87.96,73.74 89.41,75.18 94.14,75.18 94.77,74.55 97.61,74.55 98.15,75.08 U6.2 98.15,78.49 97.79,78.84 U5.6 98.58,79.73 R29.2
  BOTTOM w0.203: v1(87.96,73.48) 87.96,74.42 TP15.1
CHIP_DRV: length 15.9
  TOP w0.381: U6.7 98.15,72.49 v1(97.61,73.03) 97.64,73.03 98.15,73.53 102.01,73.53 102.39,73.91 102.39,76.76 103.1,77.47 104.65,77.47 R25.1
  BOTTOM w0.25: TP12.1 95.13,70.55 v1(97.61,73.03)
CHIP_IN: length 47.6
  TOP w0.203: R39.1 99.24,83.86 v1(98.53,83.15) 98.16,83.15 97.79,82.78 U5.1
  BOTTOM w0.203: TP2.1 126.84,93.37 J7.1 121.36,92 116.48,96.88 104.11,96.88 98.53,91.29 v1(98.53,83.15)
COIL_CHIP: length 1.8
  TOP w0.381: v1(135.25,68.75) v1(135.25,67.85) v1(135.25,66.95)
  vias: v1(118.75,79.25) v1(118.75,78.05) v1(118.75,76.85) v1(118.75,75.65) v1(118.75,74.45) v1(118.75,73.25) v1(118.75,72.05) v1(118.75,70.85) v1(122.05,78.95) v1(122.05,78.05) v1(122.05,77.15) v1(122.05,74.15) v1(122.05,73.25) v1(122.05,72.35) v1(122.95,78.95) v1(122.95,78.05) v1(122.95,77.15) v1(122.95,74.15) v1(122.95,73.25) v1(122.95,72.35) v1(123.85,78.95) v1(123.85,78.05) v1(123.85,77.15) v1(123.85,74.15) v1(123.85,73.25) v1(123.85,72.35) v1(128.35,79.25) v1(128.35,78.35) v1(128.35,77.45) v1(128.35,75.65) v1(128.35,74.75) v1(128.35,73.85) v1(128.35,72.65) v1(128.35,71.75) v1(128.35,70.85) v1(129.25,79.25) v1(129.25,78.35) v1(129.25,77.45) v1(129.25,75.65) v1(129.25,74.75) v1(129.25,73.85) v1(129.25,72.65) v1(129.25,71.75) v1(129.25,70.85) v1(130.15,79.25) v1(130.15,78.35) v1(130.15,77.45) v1(130.15,75.65) v1(130.15,74.75) v1(130.15,73.85) v1(130.15,72.65) v1(130.15,71.75) v1(130.15,70.85) v1(131.05,79.25) v1(131.05,78.35) v1(131.05,77.45) v1(131.05,75.65) v1(131.05,74.75) v1(131.05,73.85) v1(131.05,72.65) v1(131.05,71.75) v1(131.05,70.85) v1(131.95,79.25) v1(131.95,78.35) v1(131.95,77.45) v1(131.95,75.65) v1(131.95,74.75) v1(131.95,73.85) v1(131.95,72.65) v1(131.95,71.75) v1(131.95,70.85) v1(132.85,79.25) v1(132.85,78.35) v1(132.85,77.45) v1(132.85,75.65) v1(132.85,74.75) v1(132.85,73.85) v1(132.85,72.65) v1(132.85,71.75) v1(132.85,70.85) v1(133.75,79.25) v1(133.75,78.35) v1(133.75,77.45) v1(133.75,75.65) v1(133.75,74.75) v1(133.75,73.85) v1(133.75,72.65) v1(133.75,71.75) v1(135.25,63.35) v1(135.25,62.45) v1(135.25,61.55) v1(135.25,58.25) v1(135.25,57.35) v1(135.25,56.45) v1(135.25,53.15) v1(135.25,52.25) v1(135.25,51.35) v1(135.25,47.75) v1(135.25,46.85) v1(135.25,45.95) v1(136.15,68.75) v1(136.15,67.85) v1(136.15,66.95) v1(136.15,63.35) v1(136.15,62.45) v1(136.15,61.55) v1(136.15,58.25) v1(136.15,57.35) v1(136.15,56.45) v1(136.15,53.15) v1(136.15,52.25) v1(136.15,51.35) v1(136.15,47.75) v1(136.15,46.85) v1(136.15,45.95) v1(137.05,68.75) v1(137.05,67.85) v1(137.05,66.95) v1(137.05,63.35) v1(137.05,62.45) v1(137.05,61.55) v1(137.05,58.25) v1(137.05,57.35) v1(137.05,56.45) v1(137.05,53.15) v1(137.05,52.25) v1(137.05,51.35) v1(137.05,47.75) v1(137.05,46.85) v1(137.05,45.95)
COIL_SHOOT: length 0.4
  TOP w0.381: 128.76,62.56 v1(128.95,62.75)
  BOTTOM w0.381: v1(128.95,62.75) 129.06,62.63
  vias: v1(125.35,36.05) v1(125.35,35.15) v1(125.35,34.25) v1(126.25,36.05) v1(126.25,35.15) v1(126.25,34.25) v1(126.25,30.95) v1(126.25,30.05) v1(127.15,36.05) v1(127.15,35.15) v1(127.15,34.25) v1(127.15,30.95) v1(127.15,30.05) v1(128.05,65.45) v1(128.05,64.55) v1(128.05,63.65) v1(128.05,62.75) v1(128.05,61.25) v1(128.05,60.35) v1(128.05,59.15) v1(128.05,58.25) v1(128.05,57.35) v1(128.05,56.45) v1(128.05,36.05) v1(128.05,35.15) v1(128.05,34.25) v1(128.05,30.95) v1(128.05,30.05) v1(128.95,65.45) v1(128.95,64.55) v1(128.95,63.65) v1(128.95,61.25) v1(128.95,60.35) v1(128.95,59.15) v1(128.95,58.25) v1(128.95,57.35) v1(128.95,56.45) v1(128.95,36.05) v1(128.95,35.15) v1(128.95,34.25) v1(128.95,30.95) v1(128.95,30.05) v1(129.85,65.45) v1(129.85,64.55) v1(129.85,63.65) v1(129.85,62.75) v1(129.85,61.25) v1(129.85,60.35) v1(129.85,59.15) v1(129.85,58.25) v1(129.85,57.35) v1(129.85,56.45) v1(129.85,36.05) v1(129.85,35.15) v1(129.85,34.25) v1(130.75,65.45) v1(130.75,64.55) v1(130.75,63.65) v1(130.75,62.75) v1(130.75,61.25) v1(130.75,60.35) v1(130.75,59.15) v1(130.75,58.25) v1(130.75,57.35) v1(130.75,56.45)
DIS_SW: length 33.5
  TOP w0.203: Q9.1 86.49,87.86 v1(86.11,88.24) ; v1(93.88,76.28) 93.88,78.23 94.82,79.17 v1(94.92,79.17) ; U11.4 89.23,74.33 89.68,74.78 93.66,74.78 v1(93.88,74.56) ; v1(91.29,83.85) R43.2 R41.1 94.46,83.85 95.28,83.03 95.28,81.71 95.61,81.38 v1(95.61,81.37)
  BOTTOM w0.203: TP4.1 84.89,88.9 86.11,88.9 v1(86.11,88.24) 86.11,84.59 86.95,83.75 91.19,83.75 v1(91.29,83.85) ; v1(93.88,76.28) v1(93.88,74.56) ; v1(94.92,79.17) 95.61,79.86 v1(95.61,81.37)
DISCHARGE: length 4.2
  TOP w0.203: R36.1 75.54,84.71 U3.1 v1(72.72,84.71)
  BOTTOM w0.203: v1(72.72,84.71) 71.78,84.71 TP13.1
PWR_OK: length 4.7
  TOP w0.203: U12.4 89.76,79.45 90.22,78.99 91.31,78.99 91.77,78.54 U11.9
SHOOT: length 22.5
  TOP w0.203: 95.61,78.49 95.15,78.49 v1(94.64,77.98) ; 95.61,78.49 U6.4 95.61,75.95 95.25,75.59 88.57,75.59 86.69,73.71 U11.2 ; 95.61,78.49 95.91,78.79 U5.4 ; R28.2 v1(92.94,79.78)
  BOTTOM w0.203: v1(94.64,77.98) 94.64,78.16 93.01,79.78 v1(92.94,79.78) 90.53,79.78 TP16.1
SHOOT_DRV: length 14.3
  TOP w0.203: v1(96.19,68.91) 96.19,69.47 96.24,69.52
  TOP w0.381: U6.5 95.61,70.16 96.24,69.52 103.73,69.52 104.52,68.73 R17.1
  BOTTOM w0.25: TP11.1 96.19,66.71 v1(96.19,68.91)
SHOOT_IN: length 51.2
  TOP w0.203: 97.76,84.56 R40.1 v1(96.85,84.35) 96.85,84.05 95.91,83.11 U5.3
  BOTTOM w0.203: J7.3 128.46,89.46 129.26,90.26 129.26,93.66 TP1.1 128.33,94.59 119.74,94.59 116.92,97.41 103.63,97.41 98.86,92.64 98.84,92.64 98.05,91.85 98.05,85.55 v1(96.85,84.35)
VFB: length 13.2
  TOP w0.203: U4.2 75.95,75.34 C12.1 75.46,75.39 75.06,75.79 75.06,77.72 R13.2 74.22,81.29 R10.1 74.95,81.35 76.05,82.45 D8.2
N00647: length 14.7
  TOP w0.203: Q3.1 57.84,51.89 58.9,50.83 60.27,50.83 61.29,49.81 Q2.3 60.6,49.1 R14.1 60.19,47.82 D9.2 60.99,46.71 61.34,46.36 61.34,46.08 C2.2 62.23,43.51 62.64,43.1 D4.1
N02314: length 9.6
  TOP w0.203: R3.2 63.17,64.87 59.64,61.34 R6.1 ; R5.2 60.45,56.08 R4.2
N04713: length 1.5
  TOP w0.203: R4.1 62.13,52.25 Q2.1
N04752: length 2.5
  TOP w0.203: Q1.1 61.67,65.71 R3.1
N05183: length 1.8
  TOP w0.203: R1.1 58.65,67.11 Q1.3
N5273417: length 2.3
  TOP w0.203: R7.2 11.48,25.63 D5.1
N5276714: length 11.5
  TOP w0.203: R19.2 74.3,77.06 74.65,76.71 74.65,74.93 75.29,74.3 75.29,71.15 77.23,69.2 77.23,67.35 U4.8
N5277105: length 4.1
  TOP w0.203: C10.2 R19.1 73.41,75.06 U4.4
N5278068: length 6
  TOP w0.203: Q8.3 79.12,76.1 78.18,76.1 R23.2 77.22,75.13 U4.1
N5278284: length 1.5
  TOP w0.203: C12.2 R23.1
N5280051: length 3.2
  TOP w0.203: R24.1 R26.2 79.4,73.91 79.12,74.19 Q8.1
N11463163: length 3.1
  TOP w0.381: R21.2 71.55,64.36 R16.1
N11464709: length 6.9
  TOP w0.381: D7.2 78.08,63.88 77.52,64.44 R11.2 R12.2 76.81,62.64 75.72,61.54 Q4.1
N11468710: length 3.1
  TOP w0.381: U4.6 74.68,64.9 R11.1
N11471960: length 12.6
  TOP w0.203: v1(69.11,67.82) 69.47,67.82 72.64,70.99 74.19,70.99 74.68,71.48 U4.3 ; R21.1 C13.2 v1(69.11,65.96)
  BOTTOM w0.203: v1(69.11,65.96) v1(69.11,67.82)
N11488509: length 10
  TOP w0.381: 111.68,65.1 109.27,67.51 D11.2 106.45,66.5 R17.2 R20.2
N11493133: length 9.1
  TOP w0.381: Q7.1 D14.2 105.74,75.77 R25.2 R27.2
N11962195: length 0.1
  TOP w0.203: 52.35,96.55 52.4,96.5
N11967817: length 14.1
  TOP w0.203: 62.75,85.34 65.51,85.34 v1(65.56,85.29) ; 62.75,85.34 R8.1 61.87,84.55 Q5.1 58.65,84.45 D10.2 ; 62.75,85.34 62.05,84.64
  TOP w0.305: U3.4 66.14,84.71 v1(65.56,85.29)
  BOTTOM w0.203: TP14.1 65.56,84.38 v1(65.56,85.29)
N12014213: length 5.1
  TOP w0.203: C26.1 83.48,80.44 D17.2 84.01,80.44 R42.1 85.52,80.29 U12.3
N12020233: length 7
  TOP w0.203: U12.6 88.44,82.17 87.66,82.96 86.16,82.96 85.37,82.17 R42.2 84.8,82.68 D17.1
N12029339: length 1.8
  TOP w0.203: D15.2 130.26,9.58 R38.2
N12095362: length 10.6
  TOP w0.203: R34.1 96.16,89.15 94.97,87.96 R35.2 C21.1 91.77,87.67 90.98,86.88 90.98,85.52 90.32,84.86 U8.3
N12099460: length 6
  TOP w0.203: U8.1 87.86,83.69 87.3,84.25 R30.2 R32.1 R31.1 C20.2
N12127491: length 5.9
  TOP w0.203: U10.2 84.61,88.65 Q9.3 87.88,88.87 R44.1
N12133632: length 8.4
  TOP w0.203: R36.2 77.32,86.66 77.6,86.94 77.6,89.84 78.16,90.4 80.06,90.4 80.42,90.04 U10.4
N12237973: length 64.9
  TOP w0.203: v1(94.87,84.77) D18.3 95.46,84.17 94.11,85.52 R41.2
  BOTTOM w0.203: J7.6 137.46,88.55 137.46,94.46 136.09,95.84 119.46,95.84 117.28,98.02 103.38,98.02 101.7,96.34 101.63,96.34 98.35,93.07 98.35,93.05 97.45,92.15 97.45,85.85 96.85,85.25 95.35,85.25 v1(94.87,84.77)
N12300785: length 20.3
  TOP w0.203: H1.1 H1.2 ; H1.1 2.33,91.76 2.31,91.76 2.17,91.9 H1.5 ; H1.1 H1.3 ; H1.1 H1.4 ; H1.1 H1.8 ; H1.1 H1.7 ; H1.1 H1.6 ; H1.1 H1.9
N12300857: length 20.3
  TOP w0.203: 3.18,46.34 3.18,46.33 ; 3.18,46.34 H2.7 ; 3.18,46.34 H2.1 ; H2.1 H2.9 ; H2.1 H2.8 ; H2.1 H2.5 ; H2.1 H2.3 ; H2.1 H2.2 ; H2.1 H2.4 ; H2.1 H2.6
N12300959: length 20.3
  TOP w0.203: H3.1 H3.4 ; H3.1 H3.5 ; H3.1 H3.7 ; H3.1 H3.3 ; H3.1 H3.9 ; H3.1 H3.8 ; H3.1 H3.6 ; H3.1 H3.2
N12301091: length 20.3
  TOP w0.203: H4.9 H4.1 ; H4.1 H4.2 ; H4.1 H4.7 ; H4.1 H4.6 ; H4.1 H4.3 ; H4.1 H4.8 ; H4.1 H4.5 ; H4.1 H4.4
N12384738: length 2.2
  TOP w0.381: D19.1 R45.2
N12384949: length 18.1
  TOP w0.381: D21.1 79.56,21.39 80.88,20.07 84.54,20.07 88.05,16.56 R45.1
N12400429: length 38.8
  TOP w1.8: J2.1 120,18.9 116.32,18.9 111.92,23.29 U14.1

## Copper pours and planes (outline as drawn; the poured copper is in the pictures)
+5V on TOP (solid shape): 69.19,78.44 69.19,74.96 68.68,74.45 62.64,74.45 62.38,74.7 62.38,78.51 62.56,78.69 68.94,78.69
+16V on TOP (solid shape): 60.49,78.38 60.49,74.85 60.21,74.57 54.04,74.57 53.48,75.13 53.48,78.18 54.14,78.84 60.03,78.84
+16V on TOP (solid shape): outline of 608 points within 5.25,28.75 54.37,99.09
+16V_2 on TOP (solid shape): 79.43,51.28 79.43,36.55 78.41,35.53 53.82,35.53 52.52,36.84 52.52,49.45 52.57,49.45 52.92,49.81 58.5,49.81 58.8,49.5 58.8,41.99 59.31,41.48 63.42,41.48 65.2,39.7 68.25,39.7 68.71,40.16 68.71,43.1 68.25,43.56 67.54,43.56 66.98,44.12 66.98,48.26 67.31,48.59 70.23,48.59 71.12,49.48 71.12,51.54 71.53,51.94 78.77,51.94
GND on TOP (solid shape): 41.45,105.45 41.45,45.85 40.95,45.35 28.95,45.35 28.55,45.75 28.55,105.75 28.89,106.09 40.81,106.09
GND on TOP (solid shape): 12.77,44.12 13.06,43.83 13.06,40.65 11.6,39.19 11.6,37.17 11.31,36.88 6.86,36.88 6.21,37.53 6.21,43.74 6.62,44.15 12.77,44.15
GND on TOP (solid shape): 84.84,74.88 84.93,74.82 84.91,74.71 84.26,74.06 84.26,72.51 83.93,72.18 82.93,72.18 82.88,72.24 82.82,72.28 82.81,72.31 82.81,72.35 82.91,72.77 82.72,73.15 82.72,74.39 82.94,74.6 84.45,74.6 84.45,74.88
GND on TOP (solid shape): 68.39,68.1 68.47,68.06 68.49,67.98 68.47,67.77 68.52,67.58 68.53,67.55 67.84,66.85 67.84,62.23 67.51,61.91 67.51,55.73 70.28,52.96 70.28,49.71 69.98,49.4 67.31,49.4 66.42,48.51 66.42,43.84 67.11,43.15 67.89,43.15 68.15,42.9 68.15,40.67 67.87,40.39 65.74,40.39 65.28,40.84 65.28,43.84 65.05,44.07 64.01,44.07 63.73,44.35 63.85,54.05 63.25,54.95 63.25,63.35 63.83,64.8 63.98,64.8 63.98,66.26 63.85,66.26 63.85,66.48 63.98,66.48 63.98,67.94 63.85,67.94 63.85,68.1
GND on TOP (solid shape): 89.59,90.37 89.48,90.37 89.48,90.39 87.86,90.39 87.86,89.42 87.72,89.28 85.64,89.28 85.64,89.62 84.03,89.62 84.03,89.05 83.93,89.05 83.91,89.06 83.72,89.2 83.48,89.25 82.94,89.25 82.43,88.97 82.4,88.34 82.35,88.31 82.34,88.31 82.34,87.09 81.94,87.09 81.94,90.14 83.78,91.98 89.59,91.98
GND on TOP (solid shape): 89.28,79.35 89.33,79.36 89.36,79.32 89.36,79.28 90.05,78.59 91.15,78.59 91.32,78.42 91.35,78.35 91.32,78.28 91.21,78.09 91.17,77.88 91.17,76.33 91.17,76.23 91.2,76.13 91.19,76.04 91.1,75.99 88.63,75.99 88.54,76.04 88.53,76.13 88.56,76.23 88.57,76.33 88.57,77.88 88.52,78.11 88.38,78.31 88.35,78.38 88.38,78.46
GND on TOP (solid shape): 79.51,90 79.6,89.95 79.64,89.27 80.15,88.98 80.68,88.98 80.79,88.99 80.89,89.02 80.99,89.01 81.03,88.92 81.03,88.37 80.99,88.29 80.89,88.27 80.79,88.3 80.68,88.31 80.15,88.31 79.93,88.27 79.74,88.15 79.72,88.13 79.57,88.13 79.57,88.49 78,88.49 78,89.67 78.32,90
GND on TOP (solid shape): 84.64,71.75 84.75,71.78 84.82,71.68 84.82,70.65 84.81,70.64 84.81,70.23 85.05,69.91 85.24,69.82 85.44,69.79 85.53,69.73 85.51,69.62 84.93,69.04 84.93,67.08 84.66,66.81 79.98,66.81 79.98,68.53 80.79,68.53 80.79,70.97 81.81,70.97 81.81,71.38 81.92,71.38 81.94,71.36 82.25,71.16 82.62,71.17 82.79,71.25 82.93,71.38 84.27,71.38
GND on TOP (solid shape): 84.82,85.2 87.29,85.2 87.32,85.16 87.35,85.05 87.25,84.98 81.87,84.98 81.87,83.52 83.11,83.52 83.11,81.88 84.37,81.88 84.37,82.28 84.56,82.28 84.56,81.39 86.18,81.39 86.18,81.56 87.79,81.56 87.96,81.39 87.96,80.05 87.8,79.89 87.74,79.95 87.76,79.99 87.76,80.59 87.24,80.89 86.7,80.89 86.51,80.86 86.34,80.77 86.23,80.76 86.18,80.86 86.18,81.17 84.56,81.17 84.56,80.84 84.37,80.84 84.37,80.99 83.11,80.99 83.11,80.84 82.98,80.84 82.98,81.17 81.43,81.17 81.43,85.99 81.72,86.29 84.82,86.29
GND on TOP (solid shape): 94.31,83.19 94.37,83.28 94.48,83.26 94.87,82.87 94.87,81.54 94.97,81.45 94.96,81.36 94.97,81.29 94.94,81.21 94.87,81.17 92.13,81.17 92.13,81.12 91.29,81.12 90.75,81.66 90.61,81.66 90.51,81.71 90.52,81.82 90.63,82.26 90.4,82.65 90.36,82.76 90.44,82.83 90.71,82.96 90.89,83.2 90.94,83.26 91.02,83.26 91.1,83.23 91.17,83.21 91.22,83.21 91.22,83.11 94.31,83.11
GND on TOP (solid shape): 96.34,79.04 96.38,79.06 96.85,78.86 97.32,79.06 97.36,79.04 97.39,79.01 97.39,78.68 97.74,78.32 97.74,78.25 97.73,78.24 97.59,78.04 97.54,77.8 97.54,76.38 97.59,76.13 97.74,75.93 97.74,75.25 97.45,74.95 94.94,74.95 94.87,75.02 94.85,75.13 94.95,75.19 95.42,75.19 96.01,75.78 96.01,75.93 96.16,76.13 96.21,76.38 96.21,77.8 96.16,78.04 96.02,78.24 96.01,78.25 96.01,78.32 96.31,78.62 96.31,79.01
GND on TOP (solid shape): 75.46,68.73 75.46,68.4 75.43,68.36 75.4,68.31 75.31,68.26 75.22,68.31 74.54,68.64 74.07,68.05 74.07,66.62 74.1,66.44 74.19,66.27 74.19,64.69 74.4,64.48 74.4,63.63 75.87,63.63 75.87,65.25 75.17,65.25 75.17,66.27 75.2,66.31 75.22,66.36 75.31,66.42 75.4,66.36 75.43,66.31 75.46,66.27 75.46,65.96 76.11,65.31 76.08,65.25 76.08,65.25 76.08,62.6 75.33,61.85 74.35,61.85 73.75,62.45 73.75,63.35 73.45,63.65 72.21,63.65 72.21,65.25 70.74,65.25 70.74,63.65 70.53,63.65 70.53,66.77 70.3,66.77 70.21,66.83 70.23,66.95 72.77,69.49 74.7,69.49
GND on TOP (solid shape): outline of 2476 points within 50.59,36.25 148.99,109.08
GND on BOTTOM (solid shape): 89.96,71.38 90.05,71.32 90.03,71.21 90.07,70.29 90.99,70.35 91,70.36 91.07,70.36 92.77,68.66 92.77,67.24 92.7,67.15 92.59,67.17 89.97,69.79 87.07,69.79 86.98,69.85 86.98,69.95 86.85,71.05 85.75,70.99 85.3,71.07 84.91,70.83 84.78,70.39 84.98,69.97 85,69.86 84.91,69.79 82.83,69.79 81.92,70.7 81.92,71.15 81.98,71.24 82.08,71.24 82.28,71.15 82.49,71.14 82.57,71.12 82.61,71.04 82.61,70.92 82.64,70.81 83.44,70.24 84.2,70.87 84.22,71.06 84.19,71.25 84.21,71.34 84.29,71.38
GND on BOTTOM (solid shape): outline of 6575 points within 1,0.4 148.73,109.08
+BAT on TOP (solid shape): outline of 138 points within 28.28,4.8 85.99,34.7
+VCAP on TOP (solid shape): 97.95,63.75 97.95,60.15 98.95,59.15 103.15,59.15 106.6,55.7 106.6,41.3 104.05,38.75 104.05,29.45 103.45,28.85 99.25,28.85 98.95,29.15 98.95,33.65 99.55,34.25 99.55,52.55 98.65,53.45 91.75,53.45 89.95,55.25 89.95,63.75 90.55,64.35 97.35,64.35
+VCAP on TOP (solid shape): outline of 493 points within 42.55,46.15 107.12,106.15
+VCAP on BOTTOM (solid shape): 106.76,90.78 106.76,41.56 106.05,40.85 101.37,40.85 101.37,40.87 100.56,41.68 100.56,57.43 102.01,58.88 102.01,90.52 102.44,90.95 106.58,90.95
+VCOIL on TOP (solid shape): 122.05,47.45 122.05,26.75 124.15,24.65 129.55,24.65 130.75,25.85 130.75,30.65 132.25,32.15 132.55,32.15 135.7,29 138.51,26.41 139.71,26.41 141.85,28.55 141.85,29.15 135.25,35.75 135.25,36.35 136.45,37.55 137.25,37.55 141.2,33.6 142.45,32.45 145.3,29.6 145.3,27.8 137.05,19.55 130.41,19.55 128.88,21.08 122.06,21.08 122.05,21.08 119.84,21.08 113.75,27.18 108.17,27.18 108.15,27.16 106.86,27.16 105.25,28.77 105.25,37.25 108.55,40.55 108.55,47.15 109.45,48.05 121.45,48.05
+VCOIL on BOTTOM (solid shape): 122.95,47.15 122.95,25.85 124.15,24.65 129.55,24.65 130.75,25.85 130.75,30.35 132.25,31.85 132.85,31.85 133.45,31.25 136.75,28.25 138.25,26.75 140.05,26.75 141.55,28.25 141.55,29.75 135.55,35.75 135.55,36.05 136.75,37.25 137.35,37.25 145.15,29.45 145.15,27.65 137.35,19.85 124.75,19.85 114.85,29.75 105.85,29.75 105.25,30.35 105.25,35.23 109.27,39.25 109.27,47.16 110.16,48.05 122.05,48.05
COIL_CHIP on TOP (solid shape): 138.55,78.95 138.55,42.65 145.45,35.75 145.45,34.4 144.25,33.2 142.6,33.2 137.65,38.15 123.85,38.15 123.25,38.75 123.25,53.15 124.15,54.05 131.95,54.05 133.45,55.55 133.45,68.45 131.95,69.95 118.75,69.95 118.15,70.55 118.15,79.55 119.35,80.75 136.75,80.75
COIL_CHIP on BOTTOM (solid shape): 138.55,78.95 138.55,42.65 145.75,35.45 145.75,34.25 144.25,32.75 143.05,32.75 133.45,42.35 133.45,68.45 131.95,69.95 118.75,69.95 118.15,70.55 118.15,79.55 118.75,80.15 137.35,80.15
COIL_SHOOT on TOP (solid shape): 132.25,67.55 132.25,56.15 131.05,54.95 119.35,54.95 118.45,55.85 118.45,68.45 118.75,68.75 131.05,68.75
COIL_SHOOT on TOP (solid shape): 139.45,30.65 139.75,30.35 139.75,29.15 139.15,28.55 137.95,28.55 136.45,30.05 133.14,33.23 131.65,33.35 129.85,31.55 129.85,26.75 128.95,25.85 124.75,25.85 123.25,27.35 123.25,36.35 123.85,36.95 132.55,36.95
COIL_SHOOT on BOTTOM (solid shape): 131.95,66.95 131.95,37.85 140.05,29.75 140.05,29.15 138.85,27.95 138.25,27.95 133.45,32.75 130.15,32.75 129.85,32.45 129.85,28.85 129.55,28.55 125.05,28.55 124.45,29.15 124.45,66.65 125.35,67.55 131.35,67.55
N02314 on TOP (solid shape): 61.54,63.02 61.54,55.35 61.19,54.99 58.29,54.99 57.94,55.35 57.94,62.97 58.19,63.22 61.34,63.22
N11462968 on TOP (solid shape): 88.9,61.16 88.9,53.19 90.91,51.18 97.26,51.18 97.66,50.77 97.66,36.6 96.6,35.53 82.88,35.53 82.02,36.4 82.02,53.67 81.2,54.48 79.01,54.48 78.55,54.95 78.55,60.95 78.94,61.34 88.72,61.34
N11463163 on TOP (solid shape): 73.38,62.97 73.38,58.85 74.14,58.09 76.78,58.09 76.96,57.91 76.96,53.72 76.61,53.37 71.83,53.37 69.16,56.03 69.16,62.81 69.62,63.27 73.08,63.27
N11962195 on TOP (solid shape): 55.45,99.05 55.45,84.65 54.85,84.05 50.05,84.05 49.35,84.75 49.35,98.95 49.75,99.35 55.15,99.35
N12190959 on TOP (solid shape): 25.87,32.94 25.87,21.62 25.11,20.85 17.03,20.85 15.2,22.68 15.2,26.85 13.43,28.63 13.43,33.1 13.53,33.2 25.62,33.2
N12384949 on TOP (solid shape): 87.09,34.11 87.09,27.74 87,27.65 80.98,27.65 80.23,26.9 80.23,20.68 79.88,20.33 78.97,20.33 78.96,20.32 76.42,20.32 76.16,20.57 76.16,34.19 76.34,34.37 86.83,34.37

Small or netless copper shapes (teardrops, artwork), in the pictures only: 1 on TOP

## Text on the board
Ref Des/Silkscreen Bottom: SSLPwrBrd_V1.0 | PCB-00002 | 2016/06/20
Board Geometry/Soldermask Top: 2016/06/20 | SSL_PwrBrd V1_0
Ref Des/Silkscreen Top: SHOOT | CHIP
User.45: FIGURE | SIZE | 0.4064 | 0.508 | 0.9144 | 1.016 | 1.27 | 1.3208 | 1.7272 | 1.8288 | 2.032 | 3.81 | 2.032x0.4064 | DRILL CHART: $Drill$ | ALL UNITS ARE IN MILLIMETERS | PLATED | NON-PLATED | QTY | 32 | 713 | 8 | 14 | 2 | 10 | 4 | 1
